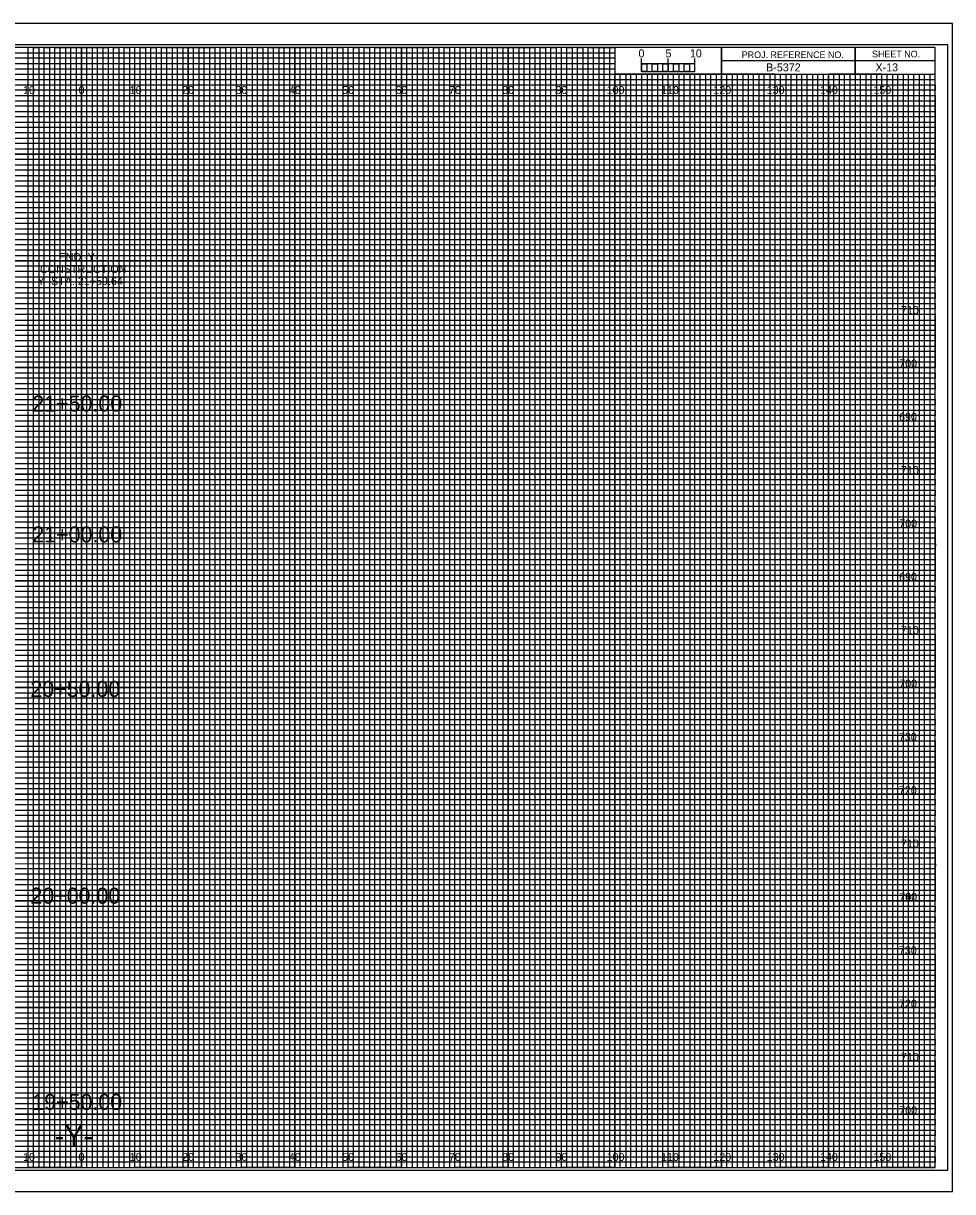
# Model space of a CAD drawing. Extents: x -13 to 323, y -4 to 434.
# Drawn here: x 149.1 to 323.3, y 215.5 to 434.5 of the extents above; entities that cross this region are included whole.
import ezdxf

# ---------------------------------------------------------------- set-up
doc = ezdxf.new("R2010")
doc.units = 0
for name, color, linetype in [('Exist XS Center Line Elevation Label', 7, 'Continuous'), ('Prop CMT Conc Surface', 7, 'Continuous'), ('Prop CMT Concrete Structures', 7, 'Continuous'), ('Prop CMT Pvmt Course 1', 7, 'Continuous'), ('Prop CMT Pvmt Course 1 CG', 7, 'Continuous'), ('Prop CMT Pvmt Course 2', 7, 'Continuous'), ('Prop CMT Pvmt Course 3', 7, 'Continuous'), ('Prop CMT Pvmt Surface', 7, 'Continuous'), ('Prop CMT Pvmt Surface Shoulder', 7, 'Continuous'), ('Prop CMT Shld Paved Course 1', 7, 'Continuous'), ('Prop CMT Shld Paved Course 2', 7, 'Continuous'), ('Prop CMT Shld Paved Course 3', 7, 'Continuous'), ('Prop CMT Slope Grass', 7, 'Continuous'), ('Prop CMT Subgrade Earthwork', 7, 'Continuous'), ('Prop XS Dump Level', 7, 'Continuous'), ('Prop XS Earthwork Shape', 7, 'Continuous'), ('Prop XS Elevation Labels', 7, 'Continuous'), ('Typical Curb CELL', 7, 'Continuous')]:
    doc.layers.add(name, color=color, linetype=linetype)

msp = doc.modelspace()

# ---------------------------------------------------------------- linework, layer by layer
at = {"layer": 'Exist XS Center Line Elevation Label'}
for p, q in [((0, 429), (260, 429)), ((260, 427.98), (0, 427.98)), ((260, 429), (260, 427.98)), ((0, 427), (260, 427)), ((260, 425.89), (0, 425.89)), ((260, 427), (260, 425.89)), ((0, 424), (320, 424))]:
    msp.add_line(p, q, dxfattribs=at)
for points in [[(0, 423), (270, 423), (320, 423), (320, 422), (0, 422)], [(0, 421), (320, 421), (320, 419), (0, 419)], [(0, 418), (320, 418), (320, 417), (0, 416.98)], [(0, 416), (320, 416), (320, 414), (0, 414)], [(0, 413), (320, 413), (320, 412), (0, 412)], [(0, 411), (320, 411), (320, 409), (0, 409)], [(0, 408), (320, 408), (320, 407), (0, 407)], [(0, 406), (320, 406), (320, 404), (0, 404)], [(0, 403), (320, 403), (320, 402), (0, 402)], [(0, 401), (320, 401), (320, 399), (0, 399)], [(0, 398), (320, 398), (320, 397), (0, 397)], [(0, 396), (320, 396), (320, 393.95), (320, 393), (320, 392), (0, 392)], [(0, 394), (320, 394), (320, 393), (0, 393)], [(0, 391), (320, 391), (320, 389), (0, 389.03)], [(0, 389.03), (320, 389), (320, 388), (0, 388)], [(0, 387), (320, 387), (320, 386), (0, 386)], [(0, 384), (320, 384), (320, 383), (0, 383)], [(0, 382), (320, 382), (320, 381), (0, 381)], [(-0.07, 378.89), (320, 378.89), (320, 377.88), (-0.07, 377.88)], [(0, 377), (320, 377), (320, 376), (0, 376)], [(0, 374), (320, 374), (320, 373), (0, 373)], [(0, 372), (320, 372), (320, 371), (0, 371)], [(0, 369), (320, 369), (320, 368), (0, 368)], [(0, 367), (320, 367), (320, 366), (0, 366)], [(0, 364), (320, 364), (320, 363), (0, 363)], [(0, 362), (320, 362), (320, 361), (0, 361)], [(0, 359), (320, 359), (319.99, 357.98), (0, 358)], [(0, 357), (320, 357), (320, 356), (0, 356)], [(0, 354), (320, 354), (320, 353), (0, 353)], [(0, 352), (320, 352), (320, 351), (0, 351)], [(0, 349), (320, 349), (320, 348), (0, 348)], [(0, 347), (320, 347), (320, 346), (0, 346)], [(0, 344), (320, 344), (320, 343), (0, 343)], [(0, 342), (320, 342), (320, 341), (0, 341)], [(0, 339), (320, 339), (320, 338), (0, 338)], [(0, 336.99), (320.07, 336.91), (320, 336), (0, 336)], [(0, 334), (320, 334), (320, 333), (0, 333)], [(0, 332), (320, 332), (320, 331), (0, 331)], [(0, 329), (320, 329), (320, 328), (0, 328)], [(0, 327), (320, 327), (320, 326), (0, 326)], [(0, 324), (320, 324), (320, 323), (0, 323)], [(0, 322), (320, 322), (320, 321), (0, 321)], [(0, 319), (320, 319), (320, 318), (0, 318)], [(0, 317), (320, 317), (320, 316), (0, 316)], [(0, 314), (320, 314), (320, 313), (0, 313)], [(0, 312), (320, 312), (320, 311), (0, 311)], [(0, 309), (320, 309), (320, 308), (0, 308)], [(0, 307), (320, 307), (320, 306), (0, 306)], [(0, 304), (320, 304), (320, 303), (0, 303)], [(0, 302), (320, 302), (320, 301), (0, 301)], [(0, 299), (320, 299), (319.99, 297.98), (0, 298)], [(0, 297), (320, 297), (320, 296), (0, 296)], [(0, 294), (320, 294), (320, 293), (0, 293)], [(0, 292), (320, 292), (320, 291), (0, 291)], [(0, 289), (320, 289), (320, 288), (0, 288)], [(0, 287), (320, 287), (320, 286), (0, 286)], [(0, 284), (320, 284), (320, 283), (0, 283)], [(0, 282), (320, 282), (320, 281), (0, 281)], [(0, 279), (320, 279), (320, 278), (0, 278)], [(0, 276.99), (320.07, 276.91), (320, 276), (0, 276)], [(0, 274), (320, 274), (320, 273), (0, 273)], [(0, 272), (320, 272), (320, 271), (0, 271)], [(0, 269), (320, 269), (320, 268), (0, 268)], [(0, 267), (320, 267), (320, 266), (0, 266)], [(0, 264), (320, 264), (320, 263), (0, 263)], [(0, 262), (320, 262), (320, 261), (0, 261)], [(0, 259), (320, 259), (320, 258), (0, 258)], [(0, 257), (320, 257), (320, 256), (0, 256)], [(0, 254), (320, 254), (320, 253), (0, 253)], [(0, 252), (320, 252), (320, 251), (0, 251)], [(0, 249), (320, 249), (320, 248), (0, 248)], [(0, 247), (320, 247), (320, 246), (0, 246)], [(0, 244), (320, 244), (320, 243), (0, 243)], [(0, 242), (320, 242), (320, 241), (0, 241)], [(0, 239), (320, 239), (320, 238), (0, 238)], [(0, 237), (320, 237), (320, 236), (0, 236)], [(0, 234), (320, 234), (320, 233), (0, 233)], [(0, 232), (320, 232), (320, 231), (0, 231)], [(0, 229), (320, 229), (320, 228), (0, 228)], [(0, 227), (320, 227), (320, 226), (0, 226)], [(0, 224), (320, 224), (320, 223), (0, 223)], [(0, 222), (320, 222), (320, 221), (0, 221)]]:
    msp.add_lwpolyline(points, dxfattribs=at)
at = {"layer": 'Prop CMT Conc Surface'}
for p, q in [((305, 430), (305, 425)), ((305, 425), (305, 430)), ((280, 427.5), (280, 425)), ((320, 427.49), (280, 427.49)), ((280, 425), (320, 425))]:
    msp.add_line(p, q, dxfattribs=at)
for points in [[(320, 430), (0, 430), (0, 220), (320, 220)], [(280, 430), (260, 430), (260, 425.03), (280, 425.03)], [(320, 430), (280, 430), (280, 425), (320, 425)]]:
    msp.add_lwpolyline(points, close=True, dxfattribs=at)
at = {"layer": 'Prop CMT Concrete Structures'}
for p, q in [((150, 220), (150, 430)), ((160, 220), (160, 430)), ((170, 220), (170, 430)), ((180, 220), (180, 430)), ((190, 220), (190, 430)), ((200, 220), (200, 430)), ((210, 220), (210, 430)), ((220, 220), (220, 430)), ((230, 220), (230, 430)), ((240, 220), (240, 430)), ((250, 220), (250, 430)), ((260, 220), (260, 424.69)), ((270, 220), (270, 424.69)), ((280, 220), (280, 424.69)), ((290, 220), (290, 424.69)), ((300, 220), (300, 424.69)), ((310, 220), (310, 424.69)), ((0, 420), (320, 420)), ((0, 410), (320, 410)), ((0, 400), (320, 400)), ((0, 390), (320, 390)), ((0, 380), (320, 380)), ((0, 370), (320, 370)), ((0, 360), (320, 360)), ((0, 350), (320, 350)), ((0, 340), (320, 340)), ((0, 330), (320, 330)), ((0, 320), (320, 320)), ((0, 310), (320, 310)), ((0, 300), (320, 300)), ((0, 290), (320, 290)), ((0, 280), (320, 280)), ((0, 270), (320, 270)), ((0, 260), (320, 260)), ((0, 250), (320, 250)), ((0, 240), (320, 240)), ((0, 230), (320, 230))]:
    msp.add_line(p, q, dxfattribs=at)
at = {"layer": 'Prop CMT Pvmt Course 2'}
msp.add_lwpolyline([(-13.4, 215.5), (323.3, 215.5), (323.3, 434.5), (-13.4, 434.5)], close=True, dxfattribs=at)
at = {"layer": 'Prop CMT Pvmt Course 3'}
msp.add_lwpolyline([(-10.8, 219.5), (322.4, 219.5), (322.4, 430.5), (-10.8, 430.5)], close=True, dxfattribs=at)
at = {"layer": 'Prop CMT Pvmt Surface'}
for p, q in [((323.3, 434.5), (-13.4, 434.5)), ((-13.4, 215.5), (323.3, 215.5))]:
    msp.add_line(p, q, dxfattribs=at)
at = {"layer": 'Prop CMT Slope Grass'}
for p, q in [((265, 425.49), (265, 427.9)), ((265, 426.9), (265, 427.9)), ((270, 425.49), (270, 427.9)), ((275, 425.49), (275, 427.9)), ((275, 426.9), (275, 427.9))]:
    msp.add_line(p, q, dxfattribs=at)
for points in [[(275, 426.9), (265, 426.9), (265, 425.49), (275, 425.49)], [(265, 426.9), (266, 426.9), (266, 425.49), (265, 425.49)], [(267, 426.9), (268, 426.9), (268, 425.49), (267, 425.49)], [(269, 426.9), (270, 426.9), (270, 425.49), (269, 425.49)], [(271, 426.9), (272, 426.9), (272, 425.49), (271, 425.49)], [(273, 426.9), (274, 426.9), (274, 425.49), (273, 425.49)]]:
    msp.add_lwpolyline(points, close=True, dxfattribs=at)
at = {"layer": 'Prop CMT Subgrade Earthwork'}
for p, q in [((267, 425), (266.01, 425)), ((266.01, 425), (266.01, 220)), ((267, 220), (267, 425)), ((269, 425), (268, 425)), ((268, 425), (268, 220)), ((269, 220), (269, 425)), ((266.01, 220), (265, 220)), ((268, 220), (267, 220))]:
    msp.add_line(p, q, dxfattribs=at)
for points in [[(150, 220), (151, 220), (151, 430), (152, 430), (152, 220)], [(152, 220), (153, 220), (153, 430), (154, 430), (154, 220)], [(155, 220), (156, 220), (156, 430), (157, 430), (157, 220)], [(157, 220), (158, 220), (158, 430), (159, 430), (159, 220)], [(160, 220), (161, 220), (161, 430), (162, 430), (162, 220)], [(162, 220), (163, 220), (163, 430), (164, 430), (164, 220)], [(165, 220), (166, 220), (166, 430), (167, 430), (167, 220)], [(167, 220), (168, 220), (168, 430), (169, 430), (169, 220)], [(170, 220), (171, 220), (171, 430), (172, 430), (172, 220)], [(172, 220), (173, 220), (173, 430), (174, 430), (174, 220)], [(175, 220), (176, 220), (176, 430), (177, 430), (177, 220)], [(177, 220), (178, 220), (178, 430), (179, 430), (179, 220)], [(180, 220), (181, 220), (181, 430), (182, 430), (182, 220)], [(182, 220), (183, 220), (183, 430), (184, 430), (184, 220)], [(185, 220), (186, 220), (186, 430), (187, 430), (187, 220)], [(187, 220), (188, 220), (188, 430), (189, 430), (189, 220)], [(190, 220), (191, 220), (191, 430), (192, 430), (192, 220)], [(192, 220), (193, 220), (193, 430), (194, 430), (194, 220)], [(195, 220), (196, 220), (196, 430), (197, 430), (197, 220)], [(197, 220), (198, 220), (198, 430), (199, 430), (199, 220)], [(200, 220), (201, 220), (201, 430), (202, 430), (202, 220)], [(202, 220), (203, 220), (203, 430), (204, 430), (204, 220)], [(205, 220), (206, 220), (206, 430), (207, 430), (207, 220)], [(207, 220), (208, 220), (208, 430), (209, 430), (209, 220)], [(210, 220), (211, 220), (211, 430), (212, 430), (212, 220)], [(212, 220), (213, 220), (213, 430), (214, 430), (214, 220)], [(215, 220), (216, 220), (216, 430), (217, 430), (217, 220)], [(217, 220), (218, 220), (218, 430), (219, 430), (219, 220)], [(220, 220), (221, 220), (221, 430), (222, 430), (222, 220)], [(222, 220), (223, 220), (223, 430), (224, 430), (224, 220)], [(225, 220), (226, 220), (226, 430), (227, 430), (227, 220)], [(227, 220), (228, 220), (228, 430), (229, 430), (229, 220)], [(230, 220), (231, 220), (231, 430), (232, 430), (232, 220)], [(232, 220), (233, 220), (233, 430), (234, 430), (234, 220)], [(235, 220), (236, 220), (236, 430), (237, 430), (237, 220)], [(237, 220), (238, 220), (238, 430), (239, 430), (239, 220)], [(240, 220), (241, 220), (241, 430), (242, 430), (242, 220)], [(242, 220), (243, 220), (243, 430), (244, 430), (244, 220)], [(245, 220), (246, 220), (246, 430), (247, 430), (247, 220)], [(247, 220), (248, 220), (248, 430), (249, 430), (249, 220)], [(250, 220), (251, 220), (251, 430), (252, 430), (252, 220)], [(252, 220), (253, 220), (253, 430), (254, 430), (254, 220)], [(255, 220), (256, 220), (256, 430), (257, 430), (257, 220)], [(257, 220), (258, 220), (258, 430), (259, 430), (259, 220)], [(260, 220), (261, 220), (261, 425), (262.02, 425), (262.02, 220)], [(262, 220), (263, 220), (263, 425), (263.99, 425), (263.99, 220)], [(270, 220), (270.98, 220), (270.98, 425), (272, 425), (272, 220)], [(272, 220), (273, 220), (273, 425), (274.05, 425), (274.05, 220)], [(275, 220), (276, 220), (276, 425), (277, 425), (277, 220)], [(277, 220), (278, 220), (278, 425), (279, 425), (279, 220)], [(280, 220), (281, 220), (281, 425), (282, 425), (282, 220)], [(282, 220), (283, 220), (283, 425), (284, 425), (284, 220)], [(285, 220), (286, 220), (286, 425), (287, 425), (287, 220)], [(287, 220), (288, 220), (288, 425), (289, 425), (289, 220)], [(290, 220), (291, 220), (291, 425), (292, 425), (292, 220)], [(292, 220), (293, 220), (293, 425), (294, 425), (294, 220)], [(295, 220), (296, 220), (296, 425), (297, 425), (297, 220)], [(297, 220), (298, 220), (298, 425), (299, 425), (299, 220)], [(300, 220), (301, 220), (301, 425), (302, 425), (302, 220)], [(302, 220), (303, 220), (303, 425), (304, 425), (304, 220)], [(305, 220), (306, 220), (306, 425), (307, 425), (307, 220)], [(307, 220), (308, 220), (308, 425), (309, 425), (309, 220)], [(310, 220), (311, 220), (311, 425), (312, 425), (312, 220)], [(312, 220), (313, 220), (313, 425), (314, 425), (314, 220)], [(315, 220), (316, 220), (316, 425), (317, 425), (317, 220)], [(317, 220), (318, 220), (318, 425), (319, 425), (319, 220)]]:
    msp.add_lwpolyline(points, dxfattribs=at)
at = {"layer": 'Prop XS Elevation Labels'}
for p, q in [((150, 430), (140, 430)), ((150, 220), (150, 430)), ((170, 430), (160, 430)), ((160, 430), (160, 220)), ((170, 220), (170, 430)), ((190, 430), (180, 430)), ((180, 430), (180, 220)), ((190, 220), (190, 430)), ((210, 430), (200, 430)), ((200, 430), (200, 220)), ((210, 220), (210, 430)), ((230, 430), (220, 430)), ((220, 430), (220, 220)), ((230, 220), (230, 430)), ((250, 430), (240, 430)), ((240, 430), (240, 220)), ((250, 220), (250, 430)), ((260, 430), (260, 220)), ((270, 220), (270, 425)), ((290, 425), (280, 425)), ((280, 425), (280, 220)), ((290, 220), (290, 425)), ((310, 425), (300, 425)), ((300, 425), (300, 220)), ((310, 220), (310, 425)), ((160, 220), (150, 220)), ((180, 220), (170, 220)), ((200, 220), (190, 220)), ((220, 220), (210, 220)), ((240, 220), (230, 220)), ((260, 220), (250, 220)), ((280, 220), (270, 220)), ((300, 220), (290, 220)), ((320, 220), (310, 220)), ((320, 220), (320, 220))]:
    msp.add_line(p, q, dxfattribs=at)
for points in [[(0, 420), (320, 420), (320, 410), (0, 410)], [(0, 400), (320, 400), (320, 390), (0, 390)], [(0, 380), (320, 380), (320, 370), (0, 370)], [(0, 360), (320, 360), (320, 350), (0, 350)], [(0, 340), (320, 340), (320, 330), (0, 330)], [(0, 320), (320, 320), (320, 310), (0, 310)], [(0, 300), (320, 300), (320, 290), (0, 290)], [(0, 280), (320, 280), (320, 270), (0, 270)], [(0, 260), (320, 260), (320, 250), (0, 250)], [(0, 240), (320, 240), (320, 230), (0, 230)]]:
    msp.add_lwpolyline(points, dxfattribs=at)
at = {"layer": 'Typical Curb CELL'}
for points in [[(145, 220), (155, 220), (155, 430), (165, 430), (165, 220), (175, 220), (175, 430), (185, 430), (185, 220), (195, 220), (195, 430), (205, 430), (205, 220), (215, 220), (215, 430), (225, 430), (225, 220), (235, 220), (235, 430), (245, 430), (245, 220), (255, 220), (255, 430), (259.93, 430), (260, 430), (260, 425), (264.99, 425), (264.99, 220), (275, 220), (275, 425), (285, 425), (285, 220), (295, 220), (295, 425), (305, 425), (305, 220), (315, 220), (315, 425)], [(0, 425), (275, 425)], [(0, 405), (320, 405), (320, 415), (0, 415)], [(0, 385), (320, 385), (320, 395), (0, 395)], [(0, 365), (320, 365), (320, 375), (0, 375)], [(0, 345), (320, 345), (320, 355), (0, 355)], [(0, 325), (320, 325), (320, 335), (0, 335)], [(0, 305), (320, 305), (320, 315), (0, 315)], [(0, 285), (320, 285), (320, 295), (0, 295)], [(0, 265), (320, 265), (320, 275), (0, 275)], [(0, 245), (320, 245), (320, 255), (0, 255)], [(0, 225), (320, 225), (320, 235), (0, 235)]]:
    msp.add_lwpolyline(points, dxfattribs=at)

# ---------------------------------------------------------------- texts
at = {"layer": 'Prop CMT Conc Surface'}
for s, p in [('PROJ. REFERENCE NO.', (283.77, 427.99)), ('SHEET NO.', (308.19, 428.12))]:
    msp.add_text(s, height=1.25, dxfattribs=at).set_placement(p)
at = {"layer": 'Prop CMT Pvmt Course 1'}
for s, p in [('21+50.00', (150.77, 361.74)), ('21+00.00', (150.77, 337.2)), ('20+50.00', (150.41, 308.23)), ('20+00.00', (150.41, 269.48)), ('19+50.00', (150.77, 230.81))]:
    msp.add_text(s, height=3, dxfattribs=at).set_placement(p)
at = {"layer": 'Prop CMT Pvmt Course 1 CG'}
for s, p in [('710', (313.61, 380)), ('700', (313.28, 370)), ('690', (313.26, 360)), ('710', (313.61, 350)), ('700', (313.28, 340)), ('690', (313.26, 330)), ('710', (313.61, 320)), ('700', (313.28, 310)), ('730', (313.22, 300)), ('720', (313.23, 290)), ('710', (313.61, 280)), ('700', (313.28, 270)), ('740', (313.3, 270)), ('730', (313.22, 260)), ('720', (313.23, 250)), ('710', (313.61, 240)), ('700', (313.28, 230))]:
    msp.add_text(s, height=1.5, dxfattribs=at).set_placement(p)
at = {"layer": 'Prop CMT Pvmt Surface Shoulder'}
for s, p in [('5', (269.47, 428.12)), ('10', (274.04, 428.12))]:
    msp.add_text(s, height=1.5, dxfattribs=at).set_placement(p)
at = {"layer": 'Prop CMT Shld Paved Course 1'}
msp.add_text('X-13', height=1.5, dxfattribs=at).set_placement((308.83, 425.5))
at = {"layer": 'Prop CMT Shld Paved Course 2'}
msp.add_text('B-5372', height=1.5, dxfattribs=at).set_placement((288.34, 425.5))
at = {"layer": 'Prop CMT Shld Paved Course 3'}
msp.add_text('-Y-', height=4, dxfattribs=at).set_placement((155, 224))
at = {"layer": 'Prop CMT Slope Grass'}
msp.add_text('0', height=1.5, dxfattribs=at).set_placement((264.41, 428.12))
at = {"layer": 'Prop XS Dump Level'}
for s, p in [('END -Y-', (155.69, 389.94)), ('CONSTRUCTION', (152.24, 387.69)), ('-Y- STA. 21+59.64', (151.07, 385.44))]:
    msp.add_text(s, height=1.5, dxfattribs=at).set_placement(p)
at = {"layer": 'Prop XS Earthwork Shape'}
for s, p in [('10', (149.04, 421.25)), ('0', (159.45, 421.25)), ('0', (159.45, 421.25)), ('10', (169.04, 421.25)), ('20', (178.86, 421.25)), ('30', (188.86, 421.25)), ('40', (198.86, 421.25)), ('50', (208.86, 421.25)), ('60', (218.86, 421.25)), ('70', (228.86, 421.25)), ('80', (238.86, 421.25)), ('90', (248.86, 421.25)), ('100', (258.44, 421.25)), ('110', (268.62, 421.25)), ('120', (278.44, 421.25)), ('130', (288.44, 421.25)), ('140', (298.44, 421.25)), ('150', (308.44, 421.25)), ('10', (149.04, 221.25)), ('0', (159.45, 221.25)), ('0', (159.45, 221.25)), ('10', (169.04, 221.25)), ('20', (178.86, 221.25)), ('30', (188.86, 221.25)), ('40', (198.86, 221.25)), ('50', (208.86, 221.25)), ('60', (218.86, 221.25)), ('70', (228.86, 221.25)), ('80', (238.86, 221.25)), ('90', (248.86, 221.25)), ('100', (258.44, 221.25)), ('110', (268.62, 221.25)), ('120', (278.44, 221.25)), ('130', (288.44, 221.25)), ('140', (298.44, 221.25)), ('150', (308.44, 221.25))]:
    msp.add_text(s, height=1.5, dxfattribs=at).set_placement(p)

doc.saveas('drawing.dxf')
